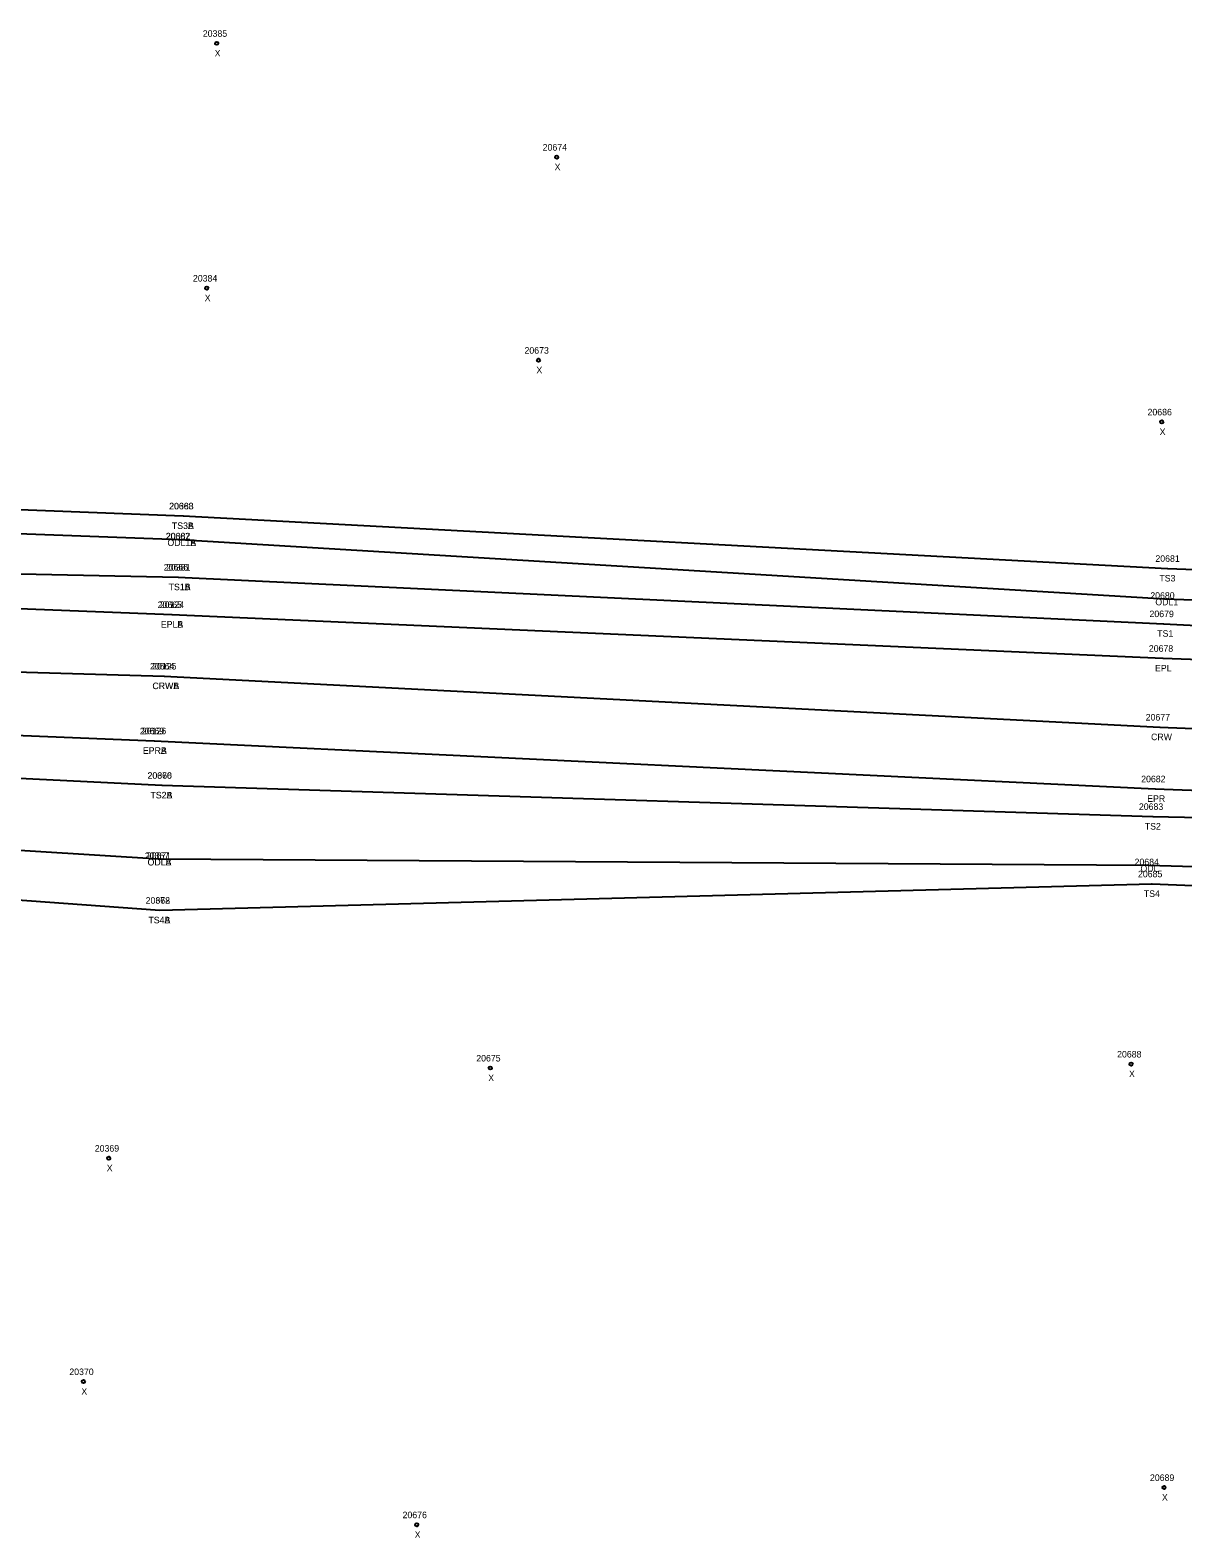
# Model space of a CAD drawing. Extents: x 1966740 to 1969291, y 1117378 to 1118461.
# Drawn here: x 1968508.9 to 1968685, y 1117784.6 to 1118015 of the extents above; entities that cross this region are included whole.
import ezdxf

# ---------------------------------------------------------------- set-up
doc = ezdxf.new("R2010")
doc.units = 0
for name, color, linetype in [('RD_DTM_BkLn1', 7, 'Continuous'), ('RD_DTM_BkLn2', 7, 'Continuous'), ('RD_EX_H2O', 7, 'Continuous'), ('RD_EX_H2O_txCode', 7, 'Continuous'), ('RD_EX_Road', 7, 'Continuous'), ('RD_EX_Road_txCode', 7, 'Continuous'), ('RD_SMD_Locator', 7, 'Continuous'), ('RD_SMD_Misc', 7, 'Continuous')]:
    doc.layers.add(name, color=color, linetype=linetype)

msp = doc.modelspace()

# ---------------------------------------------------------------- linework, layer by layer
at = {"layer": 'RD_DTM_BkLn1'}
for points in [[(1967878.98, 1117895.46), (1967922.07, 1117909.4), (1967968.89, 1117921.38), (1968013.49, 1117926.44), (1968059.29, 1117929.05), (1968105.63, 1117929.86), (1968159.12, 1117928.97), (1968212.65, 1117927.25), (1968318.5, 1117923.95), (1968422.42, 1117919.39), (1968529.36, 1117916.3)], [(1968529.36, 1117916.3), (1968681.48, 1117908.5), (1968781.89, 1117904.51), (1968887.49, 1117900.39), (1968989.06, 1117896.4), (1969090.87, 1117891.24), (1969190.23, 1117887.94), (1969284.4, 1117884.73)]]:
    msp.add_lwpolyline(points, dxfattribs=at)
at = {"layer": 'RD_DTM_BkLn2'}
for points in [[(1968378.68, 1117946.52), (1968423.07, 1117945.03), (1968532.27, 1117940.77)], [(1967874.77, 1117908.42), (1967879.51, 1117916.91), (1967881.27, 1117924.39), (1967885.24, 1117929.22), (1967913.7, 1117935.63), (1967966.11, 1117937.12), (1968012.39, 1117940.75), (1968059.42, 1117941.87), (1968105.44, 1117943.27), (1968158.32, 1117942.95), (1968212.48, 1117942.1), (1968371.25, 1117933.41), (1968422.85, 1117933.68), (1968531.49, 1117931.42)], [(1968532.27, 1117940.77), (1968682.68, 1117932.75), (1968784.38, 1117929.07), (1968872.44, 1117926.13)], [(1968531.49, 1117931.42), (1968682.06, 1117924.3), (1968783.42, 1117919.17), (1968888.7, 1117914.33), (1968991.06, 1117912.02), (1969093.07, 1117907.16), (1969191.83, 1117902.92), (1969283.72, 1117899.63)], [(1967884.1, 1117882.92), (1967891.06, 1117879.24), (1967898.84, 1117879.11), (1967924.17, 1117888.04), (1967954.33, 1117900.3), (1967970.81, 1117903.15), (1968012.93, 1117910.83), (1968059.62, 1117915.05), (1968105.25, 1117916.2), (1968157.57, 1117912.09), (1968210.74, 1117910.77), (1968320.32, 1117907.54), (1968423.18, 1117904.83), (1968528.99, 1117899.6)], [(1968528.99, 1117899.6), (1968680.45, 1117894.84), (1968781.74, 1117892.71), (1968887.7, 1117888.94), (1968987.81, 1117885.08), (1969089.75, 1117880.01), (1969189.02, 1117876.39), (1969282.76, 1117873.05)], [(1968058.02, 1117883.74), (1968104.17, 1117887.52), (1968156.67, 1117888.05), (1968209.1, 1117889.3), (1968320.79, 1117888.13), (1968422.17, 1117888.28), (1968528.68, 1117880.51)], [(1968528.68, 1117880.51), (1968680.3, 1117884.55), (1968781.05, 1117880.46), (1968887.57, 1117875.57), (1968986, 1117872.85), (1969087.95, 1117867.56), (1969189.32, 1117864.4), (1969289.73, 1117862.33)]]:
    msp.add_lwpolyline(points, dxfattribs=at)
at = {"layer": 'RD_EX_H2O'}
for points in [[(1968373.17, 1117942.71), (1968423.04, 1117941.19), (1968531.76, 1117937.18)], [(1968531.76, 1117937.18), (1968682.22, 1117928.11), (1968784.28, 1117924.56), (1968890.2, 1117919.49), (1968991.22, 1117915.37), (1969093.76, 1117910.9), (1969192.08, 1117906.24), (1969283.24, 1117903.06)], [(1968371.06, 1117895.25), (1968422.79, 1117894.92), (1968528.55, 1117888.35)], [(1968528.55, 1117888.35), (1968679.78, 1117887.39), (1968780.67, 1117884.45), (1968887.36, 1117880.9), (1968987.02, 1117877.31), (1969088.58, 1117870.53), (1969189.53, 1117868.6), (1969284.94, 1117865.64)]]:
    msp.add_lwpolyline(points, dxfattribs=at)
at = {"layer": 'RD_EX_Road'}
for points in [[(1967878.98, 1117895.46), (1967875.66, 1117903.48), (1967919.49, 1117917.47), (1967966.4, 1117928.95), (1968012.66, 1117935.42), (1968058.94, 1117938.37), (1968105.99, 1117939.39), (1968158.7, 1117938.56), (1968212.05, 1117937.21), (1968318.79, 1117933.28), (1968422.76, 1117929.93), (1968530.54, 1117925.7)], [(1968530.54, 1117925.7), (1968681.97, 1117919.01), (1968783.23, 1117915.36), (1968888.64, 1117911.44), (1968991.22, 1117907.09), (1969091.98, 1117903.06), (1969191.09, 1117898.66), (1969283.27, 1117895.43)], [(1967878.98, 1117895.46), (1967883.11, 1117885.63), (1967924.99, 1117899.59), (1967970.68, 1117910.78), (1968014.42, 1117916.56), (1968059.13, 1117919.49), (1968105.39, 1117920.31), (1968159.16, 1117919.37), (1968212.5, 1117917.97), (1968317.55, 1117914.44), (1968421.52, 1117910.75), (1968527.82, 1117906.41)], [(1968527.82, 1117906.41), (1968680.79, 1117899.07), (1968781.71, 1117895.37), (1968887.86, 1117891.84), (1968988.65, 1117888.23), (1969090.1, 1117882.83), (1969189.3, 1117879.04), (1969282.94, 1117875.42)]]:
    msp.add_lwpolyline(points, dxfattribs=at)
at = {"layer": 'RD_SMD_Locator'}
for centre, radius in [((1968537.39, 1118012.98), 0.25), ((1968589.34, 1117995.59), 0.25), ((1968535.88, 1117975.58), 0.25), ((1968586.56, 1117964.56), 0.25), ((1968681.79, 1117955.13), 0.25), ((1968532.27, 1117940.77), 0.001), ((1968532.27, 1117940.77), 0.001), ((1968531.76, 1117937.18), 0.001), ((1968531.76, 1117937.18), 0.001), ((1968682.68, 1117932.75), 0.001), ((1968531.49, 1117931.42), 0.001), ((1968531.49, 1117931.42), 0.001), ((1968682.22, 1117928.11), 0.001), ((1968530.54, 1117925.7), 0.001), ((1968530.54, 1117925.7), 0.001), ((1968682.06, 1117924.3), 0.001), ((1968681.97, 1117919.01), 0.001), ((1968529.36, 1117916.3), 0.001), ((1968529.36, 1117916.3), 0.001), ((1968681.48, 1117908.5), 0.001), ((1968527.82, 1117906.41), 0.001), ((1968527.82, 1117906.41), 0.001), ((1968528.99, 1117899.6), 0.001), ((1968528.99, 1117899.6), 0.001), ((1968680.79, 1117899.07), 0.001), ((1968680.45, 1117894.84), 0.001), ((1968528.55, 1117888.35), 0.001), ((1968528.55, 1117888.35), 0.001), ((1968679.78, 1117887.39), 0.001), ((1968680.3, 1117884.55), 0.001), ((1968528.68, 1117880.51), 0.001), ((1968528.68, 1117880.51), 0.001), ((1968677.11, 1117857.01), 0.25), ((1968579.19, 1117856.4), 0.25), ((1968520.9, 1117842.62), 0.25), ((1968517.02, 1117808.48), 0.25), ((1968682.14, 1117792.3), 0.25), ((1968567.95, 1117786.61), 0.25)]:
    msp.add_circle(centre, radius, dxfattribs=at)

# ---------------------------------------------------------------- texts
at = {"layer": 'RD_EX_H2O_txCode'}
for s, p in [('20667', (1968529.59, 1117937.18)), ('20382', (1968529.64, 1117937.18)), ('ODL1A', (1968529.86, 1117936.18)), ('ODL1B', (1968529.87, 1117936.18)), ('20680', (1968680.04, 1117928.11)), ('ODL1', (1968680.81, 1117927.11)), ('20367', (1968526.41, 1117888.35)), ('20671', (1968526.69, 1117888.35)), ('ODLA', (1968526.82, 1117887.35)), ('ODLB', (1968526.83, 1117887.35)), ('20684', (1968677.64, 1117887.39)), ('ODL', (1968678.54, 1117886.39))]:
    msp.add_text(s, height=1, dxfattribs=at).set_placement(p)
at = {"layer": 'RD_EX_Road_txCode'}
for s, p in [('20665', (1968528.37, 1117926.7)), ('20124', (1968528.7, 1117926.7)), ('EPLA', (1968528.85, 1117923.7)), ('EPLB', (1968528.86, 1117923.7)), ('20678', (1968679.82, 1117920.01)), ('EPL', (1968680.76, 1117917.01)), ('20669', (1968525.65, 1117907.41)), ('20126', (1968525.96, 1117907.41)), ('EPRA', (1968526.1, 1117904.41)), ('EPRB', (1968526.12, 1117904.41)), ('20682', (1968678.65, 1117900.07)), ('EPR', (1968679.57, 1117897.07))]:
    msp.add_text(s, height=1, dxfattribs=at).set_placement(p)
at = {"layer": 'RD_SMD_Misc'}
for s, p in [('20385', (1968535.27, 1118013.98)), ('X', (1968537.08, 1118010.98)), ('20674', (1968587.2, 1117996.59)), ('X', (1968589.02, 1117993.59)), ('20384', (1968533.76, 1117976.58)), ('X', (1968535.56, 1117973.58)), ('20673', (1968584.42, 1117965.56)), ('X', (1968586.24, 1117962.56)), ('20686', (1968679.62, 1117956.13)), ('X', (1968681.47, 1117953.13)), ('20668', (1968530.11, 1117941.77)), ('20383', (1968530.15, 1117941.77)), ('TS3A', (1968530.54, 1117938.77)), ('TS3B', (1968530.55, 1117938.77)), ('20666', (1968529.3, 1117932.42)), ('20381', (1968529.66, 1117932.42)), ('20681', (1968680.82, 1117933.75)), ('TS1A', (1968530.04, 1117929.42)), ('TS1B', (1968530.06, 1117929.42)), ('TS3', (1968681.43, 1117930.75)), ('20679', (1968679.92, 1117925.3)), ('TS1', (1968681.1, 1117922.3)), ('20664', (1968527.2, 1117917.3)), ('20125', (1968527.53, 1117917.3)), ('CRWA', (1968527.56, 1117914.3)), ('CRWB', (1968527.58, 1117914.3)), ('20677', (1968679.34, 1117909.5)), ('CRW', (1968680.16, 1117906.5)), ('20670', (1968526.81, 1117900.6)), ('20366', (1968526.83, 1117900.6)), ('TS2A', (1968527.26, 1117897.6)), ('TS2B', (1968527.28, 1117897.6)), ('20683', (1968678.3, 1117895.84)), ('TS2', (1968679.2, 1117892.84)), ('20685', (1968678.16, 1117885.55)), ('20368', (1968526.54, 1117881.51)), ('20672', (1968526.54, 1117881.51)), ('TS4', (1968679.05, 1117882.55)), ('TS4A', (1968526.95, 1117878.51)), ('TS4B', (1968526.96, 1117878.51)), ('20688', (1968674.97, 1117858.01)), ('20675', (1968577.05, 1117857.4)), ('X', (1968578.88, 1117854.4)), ('X', (1968676.79, 1117855.01)), ('20369', (1968518.76, 1117843.62)), ('X', (1968520.59, 1117840.62)), ('20370', (1968514.87, 1117809.48)), ('X', (1968516.71, 1117806.48)), ('20689', (1968679.99, 1117793.3)), ('X', (1968681.82, 1117790.3)), ('20676', (1968565.79, 1117787.61)), ('X', (1968567.64, 1117784.61))]:
    msp.add_text(s, height=1, dxfattribs=at).set_placement(p)

doc.saveas('drawing.dxf')
